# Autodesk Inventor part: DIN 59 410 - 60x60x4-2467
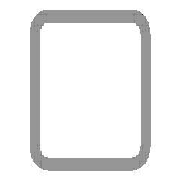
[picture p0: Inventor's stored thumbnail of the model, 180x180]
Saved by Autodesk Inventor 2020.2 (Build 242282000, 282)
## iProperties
Manager: www.cadconsulting.pl
Company: Fabian Stasiak CAD Consulting
IsCustomPart: 1
_CCFamilyMember: 60
_CCFamilyDisplayName: DIN 59410 (Kwadrat) - Rurki stalowe o przekroju kwadratowym formowane na gorąco
_FrameMemberDoc: Frame Member File
_Version: 15.0.0
_GetPNFromCC: 1
Created: 2015-01
Part Number: DIN 59 410 - 60x60x4-2467
Material: Stal, miękka
Description: Rurki stalowe o przekroju kwadratowym formowane na gorąco
Document SubType Name: Modellieren
Standard: DIN
Designer: F.Stasiak
Standards Organization: DIN
Language: pl-PL
Size Designation: 60x60x4
Categories: <MemberInstance><Categories><Category DisplayName="Kształtowniki konstrukcyjne" InternalName="089c4875-fa83-4c05-b084-43b9cc11f5ed" Mnemonic="GRDR"><CategoryPar
Stock Number: 60x60x4
Density: 7.85 g/cm^3
Appearance: Częściowo polerowana
Mass: 23928.9 g
Surface Area: 12217.8 cm^2
Volume: 3048.27 cm^3
Catalog Web Link: www.expertbooks.pl
G_L: 2467,000 mm
G_W: 60,000 mm
G_H: 60,000 mm
+28AAF3A0-C76F-464E-B37F-38C41AFF3624+CUTDETAIL1: Wytnij
Author: F.Stasiak
Subject: Zbiór ćwiczeń. Autodesk Inventor 2020. Kurs Professional
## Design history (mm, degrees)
node "Płaszczyzna początkowa"
node "Płaszczyzna końcowa"
sketch "Szkic1"
  geometry: L1 (-22, 30)-(22, 30); L2 (30, 22)-(30, -22); L3 (22, -30)-(-22, -30); L4 (-30, -22)-(-30, 22); L5 (-51.899, 0)-(51.899, 0) reference; L6 (0, -51.899)-(0, 51.899) reference; L7 (-22, 26)-(22, 26); L8 (26, 22)-(26, -22); L9 (22, -26)-(-22, -26); L10 (-26, -22)-(-26, 22); A1 r 8 centre (-22, 22) between (-22, 30) and (-30, 22); A2 r 8 centre (22, 22) between (30, 22) and (22, 30); A3 r 8 centre (22, -22) between (22, -30) and (30, -22); A4 r 8 centre (-22, -22) between (-30, -22) and (-22, -30); A5 r 4 centre (-22, 22) between (-22, 26) and (-26, 22); A6 r 4 centre (22, 22) between (26, 22) and (22, 26); A7 r 4 centre (22, -22) between (22, -26) and (26, -22); A8 r 4 centre (-22, -22) between (-26, -22) and (-22, -26); 3 further points
  constraints: 16 end point, 16 point on circle, 8 centre point, 8 tangent, 6 point on line, 4 parallel, 3 equal radius, 3 perpendicular, 1 horizontal, 7 other
  dimensions: "b" = 60 distance of point (-30, 30) point (30, 30); "msp_r" = 8 radius of A1 (= 2 x ParT); "d8" = 30 distance between parallel lines of L4 L6 (= d9); "d9" = 30 distance between parallel lines of L3 L5 (= 0.5 x b); "d10" = 4 distance between parallel lines of L3 L9 (= ParT)
extrude "Bryła" new body sketch "Szkic1" taper "d4" = 0 deg; stored distance "NLG" = 10
node "Driven Length"
  sketch "Sketch2"
    geometry: L1 (0, 0)-(10, 0) reference
    constraints: 2 end point, 1 horizontal
  workplane "Work Plane3"
  sketch "Sketch3"
    geometry: L1 (-2, 0)-(12, 0) reference; L2 (-2, 2467)-(12, 2467) reference
    dimensions: "d14" = 2467 distance between parallel lines of L1 L2 (derived)
node "Płaszczyzna konstrukcyjna4"
feature "Podział1"
body "Solid1"
other parameters: "ParT" = 4, "G_OFFSET_START" = 0 [user parameter; used in 1 equation term], "G_OFFSET_END" = -33 [user parameter; used in 1 equation term], "d11" = 0 (computed from G_OFFSET_START), "d12" = 2467 (= G_OFFSET_END + B_L), "G_L" = 2467 (= d14) [user parameter], "d13" = 90 deg
